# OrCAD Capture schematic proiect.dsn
size A
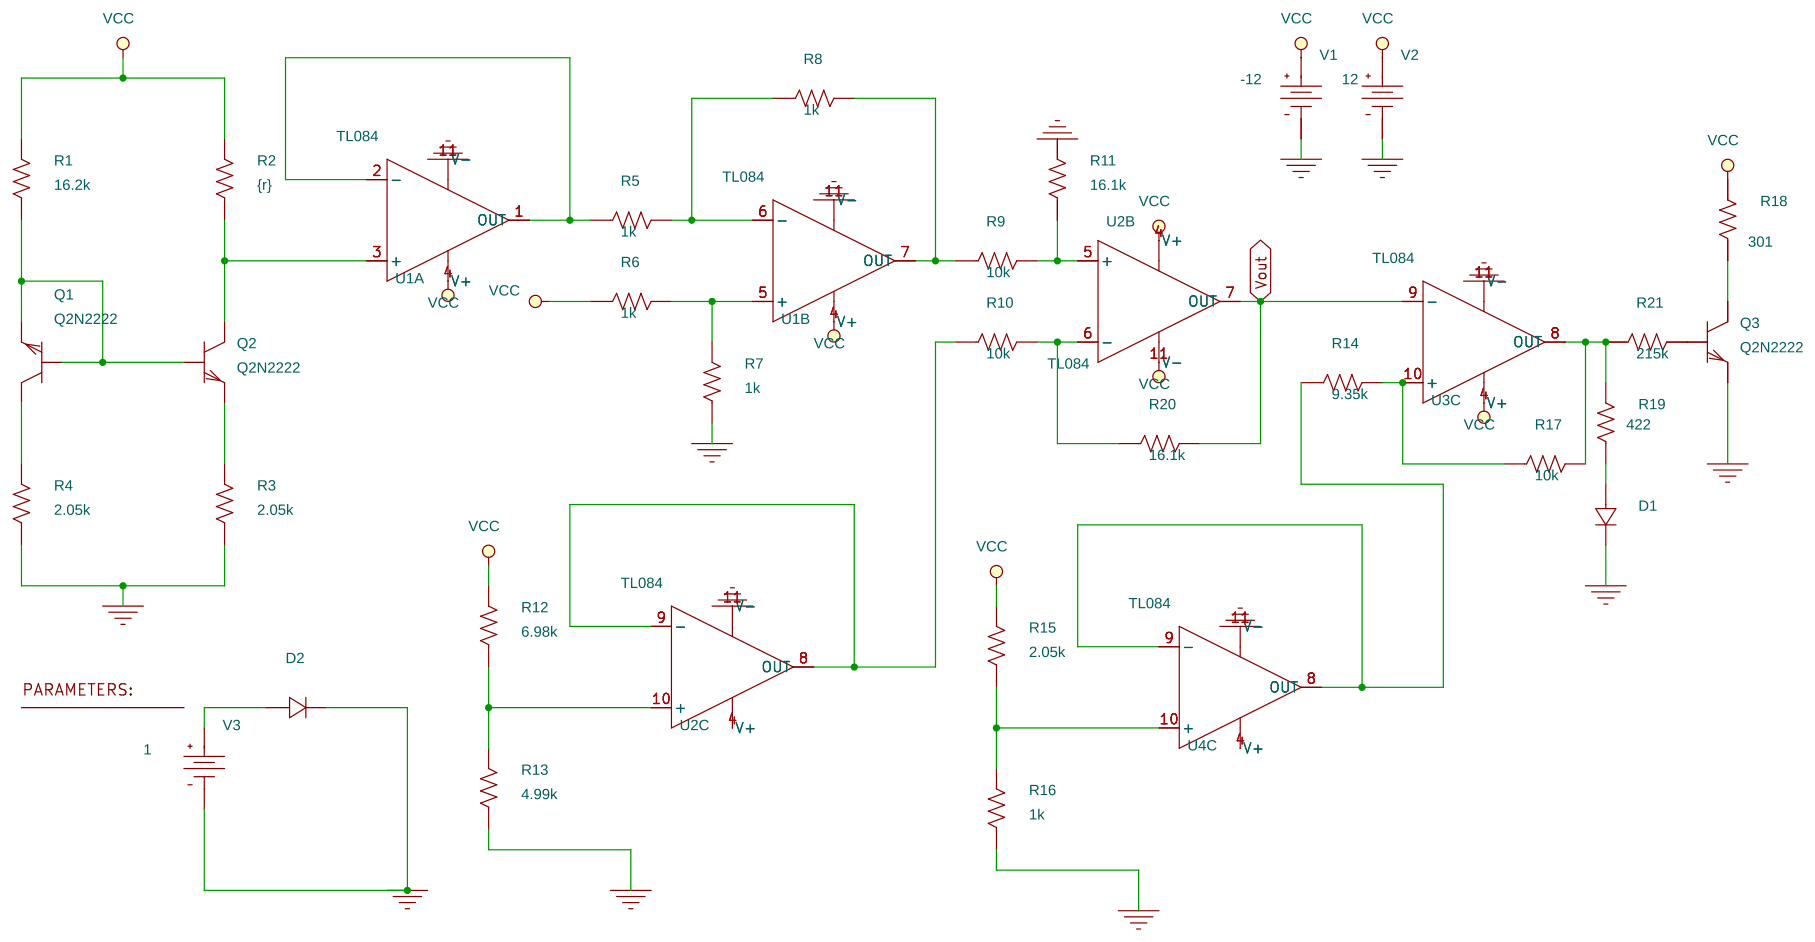
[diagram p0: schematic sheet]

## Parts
1  PARAM
D1  Dbreak
D2  Dbreak
Q1  Q2N2222  [TO18]
Q2  Q2N2222  [TO18]
Q3  Q2N2222  [TO18]
R1  16.2k  [AXRC05]
R2  {r}  [AXRC05]
R3  2.05k  [AXRC05]
R4  2.05k  [AXRC05]
R5  1k  [AXRC05]
R6  1k  [AXRC05]
R7  1k  [AXRC05]
R8  1k  [AXRC05]
R9  10k  [AXRC05]
R10  10k  [AXRC05]
R11  16.1k  [AXRC05]
R12  6.98k  [AXRC05]
R13  4.99k  [AXRC05]
R14  9.35k  [AXRC05]
R15  2.05k  [AXRC05]
R16  1k  [AXRC05]
R17  10k  [AXRC05]
R18  301  [AXRC05]
R19  422  [AXRC05]
R20  16.1k  [AXRC05]
R21  215k  [AXRC05]
U1  TL084  [DIP10014W300L800]  (sections A,B)
U2  TL084  [DIP10014W300L800]  (sections B,C)
U3  TL084  [DIP10014W300L800]  (section C)
U4  TL084  [DIP10014W300L800]  (section C)
V1  VDC
V2  VDC
V3  VDC

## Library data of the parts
1 = PARAM: r: 8k
D1 D2 = Dbreak: PSpiceTemplate: D^@REFDES  %1 %2 @MODEL ?AREA/@AREA/
Q1-Q3 = Q2N2222
R1-R21 = R: TOLERANCE: 1%
U1-U4 = TL084
V1 = VDC: DC: -12
V2 = VDC: DC: 12
V3 = VDC: DC: 1

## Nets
-VCC: D1.1(2) D2.1(2) Q3.1(e) R3.1 R4.1 R7.1 R11.2 R13.1 R16.1 U1.11(V-) U2.11(V-) U3.11(V-) U4.11(V-) V1.0(+) V1.1(-) V2.1(-) V3.1(-)
V+: R1.2 R2.2 R6.1 R12.2 R15.2 R18.2 U1.4(V+) U2.4(V+) U3.4(V+) U4.4(V+) V2.0(+)
Vout: R20.2 U2.7(OUT) U3.9(-)
N14396: Q1.1(e) Q1.2(b) Q2.2(b) R1.1
N14518: Q2.3(c) R2.1 U1.3(+)
N14528: Q2.1(e) R3.2
N14590: Q1.3(c) R4.2
N14739: R5.1 U1.1(OUT) U1.2(-)
N15137: R6.2 R7.2 U1.5(+)
N15169: R5.2 R8.1 U1.6(-)
N15278: R8.2 R9.1 U1.7(OUT)
N15430: R9.2 R11.1 U2.5(+)
N15514: R10.2 R20.1 U2.6(-)
N15599: R10.1 U2.8(OUT) U2.9(-)
N15893: R12.1 R13.2 U2.10(+)
N16389: R14.2 R17.1 U3.10(+)
N16827: R14.1 U4.8(OUT) U4.9(-)
N16901: R15.1 R16.2 U4.10(+)
N17291: R17.2 R19.2 R21.1 U3.8(OUT)
N17449: D1.0(1) R19.1
N17475: Q3.3(c) R18.1
N18195: D2.0(1) V3.0(+)
N27001: Q3.2(b) R21.2
